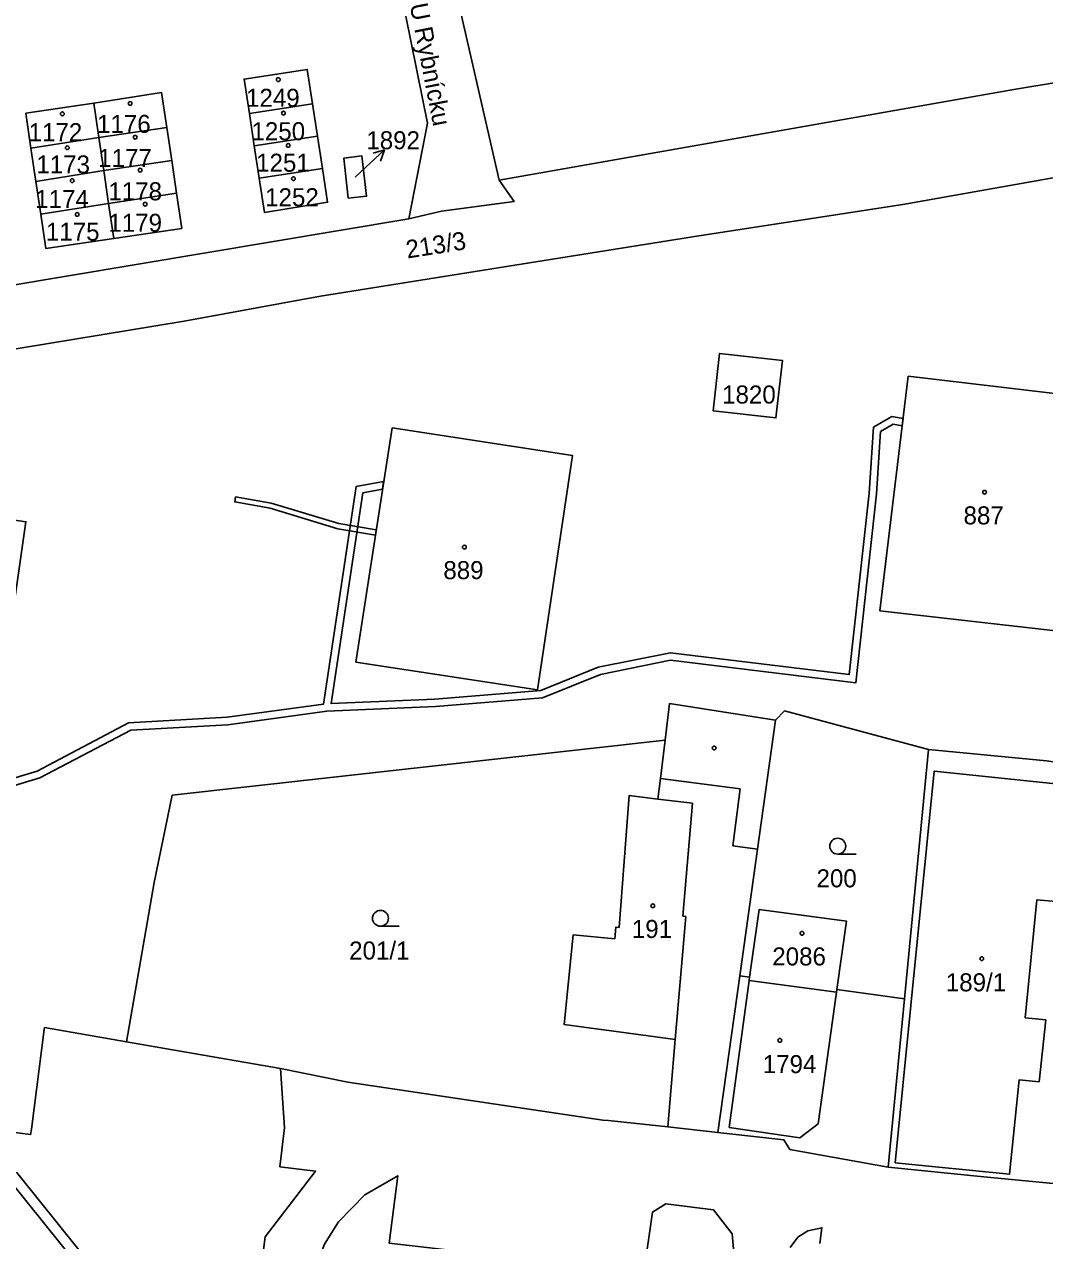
# Model space of a CAD drawing. Extents: x -680203 to -673936, y -1102717 to -1093650.
# Drawn here: x -679164.9 to -679068.7, y -1098436.4 to -1098321.8 of the extents above; entities that cross this region are included whole.
import ezdxf

# ---------------------------------------------------------------- set-up
doc = ezdxf.new("R2010")
doc.units = 0
for name, color, linetype in [('SOxx02xx_Staničení_Popis10', 7, 'Continuous'), ('SOxxxxxx_Koleje_hlavní_body_Popis10', 7, 'Continuous'), ('SOxxxxxx_Koleje_LN_parametry_Popis10', 7, 'Continuous'), ('SOxxxxxx_Koleje_param další_Popis10', 7, 'Continuous'), ('SOxxxxxx_Osa_bod_P', 7, 'Continuous'), ('SOxxxxxx_Staničení_Popis10', 7, 'Continuous'), ('x_prac', 7, 'Continuous')]:
    doc.layers.add(name, color=color, linetype=linetype)

msp = doc.modelspace()

# ---------------------------------------------------------------- linework, layer by layer
at = {"layer": 'SOxx02xx_Staničení_Popis10'}
for p, q in [((-679133.11, -1098335.71), (-679130.92, -1098333.66)), ((-679130.92, -1098333.66), (-679131.99, -1098333.98)), ((-679130.92, -1098333.66), (-679131.31, -1098334.71)), ((-679133.67, -1098336.24), (-679133.11, -1098335.71))]:
    msp.add_line(p, q, dxfattribs=at)
at = {"layer": 'SOxxxxxx_Koleje_hlavní_body_Popis10'}
for p, q in [((-679088.19, -1098400.02), (-679086.44, -1098400.02)), ((-679131.3, -1098406.82), (-679129.55, -1098406.82))]:
    msp.add_line(p, q, dxfattribs=at)
for centre in [(-679088.19, -1098399.27), (-679131.3, -1098406.07)]:
    msp.add_circle(centre, 0.75, dxfattribs=at)
at = {"layer": 'SOxxxxxx_Koleje_LN_parametry_Popis10'}
for points in [[(-679169.77, -1098394.76), (-679163.4, -1098392.84), (-679154.84, -1098388.33), (-679145.7, -1098387.83), (-679136.34, -1098386.56), (-679126.11, -1098386.12), (-679116.01, -1098385.29), (-679110.56, -1098383.08), (-679103.94, -1098381.75), (-679086.49, -1098383.88), (-679084.52, -1098366.07), (-679084.15, -1098360.21), (-679082.96, -1098359.52), (-679082.11, -1098359.66), (-679082.02, -1098358.97), (-679083.1, -1098358.79), (-679084.82, -1098359.8)], [(-679084.82, -1098359.8), (-679085.22, -1098366.01), (-679087.1, -1098383.1), (-679103.97, -1098381.04), (-679110.76, -1098382.41), (-679116.17, -1098384.6), (-679126.16, -1098385.42), (-679135.96, -1098385.84), (-679132.97, -1098365.98), (-679131.11, -1098365.64), (-679131, -1098364.91), (-679133.59, -1098365.38), (-679136.68, -1098385.9), (-679145.76, -1098387.13), (-679155.04, -1098387.64), (-679163.66, -1098392.19), (-679169.84, -1098394.05)], [(-679150.01, -1098449.39), (-679165.6, -1098430)], [(-679166.4, -1098430.6), (-679151.03, -1098449.71)]]:
    msp.add_lwpolyline(points, dxfattribs=at)
msp.add_lwpolyline([(-679144.95, -1098366.34), (-679145.04, -1098366.83), (-679141.71, -1098367.43), (-679135.32, -1098369.36), (-679131.78, -1098369.95), (-679131.7, -1098369.46), (-679135.21, -1098368.87), (-679141.59, -1098366.95)], close=True, dxfattribs=at)
at = {"layer": 'SOxxxxxx_Koleje_param další_Popis10'}
for centre in [(-679140.93, -1098327.04), (-679154.9, -1098329.28), (-679161.29, -1098330.26), (-679140.45, -1098330.19), (-679154.42, -1098332.47), (-679160.82, -1098333.46), (-679139.99, -1098333.24), (-679153.96, -1098335.57), (-679160.36, -1098336.56), (-679139.5, -1098336.37), (-679159.89, -1098339.74), (-679153.49, -1098338.78), (-679074.35, -1098365.92), (-679123.39, -1098371.09), (-679099.84, -1098390.02), (-679105.62, -1098404.89), (-679091.56, -1098407.48), (-679074.61, -1098409.87), (-679093.65, -1098417.57)]:
    msp.add_circle(centre, 0.175, dxfattribs=at)
at = {"layer": 'SOxxxxxx_Staničení_Popis10'}
for p, q in [((-679097.39, -1098393.87), (-679104.91, -1098392.9)), ((-679098.08, -1098399.23), (-679097.39, -1098393.87)), ((-679105.14, -1098394.84), (-679101.87, -1098395.23)), ((-679101.87, -1098395.23), (-679102.8, -1098405.87)), ((-679095.74, -1098399.55), (-679098.08, -1098399.23)), ((-679102.5, -1098405.9), (-679103.51, -1098417.49)), ((-679102.8, -1098405.87), (-679102.5, -1098405.9)), ((-679098.43, -1098425.79), (-679096.55, -1098411.92)), ((-679088.3, -1098413.04), (-679090.03, -1098425.43)), ((-679090.03, -1098425.43), (-679091.76, -1098426.74)), ((-679091.76, -1098426.74), (-679098.43, -1098425.79))]:
    msp.add_line(p, q, dxfattribs=at)
at = {"layer": 'x_prac'}
for p, q in [((-679125.78, -1098311.74), (-679120.11, -1098336.51)), ((-679157.85, -1098332.5), (-679158.33, -1098329.25)), ((-679143.65, -1098330.22), (-679137.7, -1098329.31)), ((-679143.65, -1098330.22), (-679143.19, -1098333.27)), ((-679137.24, -1098332.36), (-679137.7, -1098329.31)), ((-679157.85, -1098332.5), (-679151.44, -1098331.55)), ((-679150.98, -1098334.65), (-679151.44, -1098331.55)), ((-679164.25, -1098333.5), (-679157.85, -1098332.5)), ((-679157.39, -1098335.6), (-679157.85, -1098332.5)), ((-679143.19, -1098333.27), (-679137.24, -1098332.36)), ((-679136.77, -1098335.41), (-679137.24, -1098332.36)), ((-679164.25, -1098333.5), (-679163.78, -1098336.65)), ((-679143.19, -1098333.27), (-679142.72, -1098336.32)), ((-679157.39, -1098335.6), (-679150.98, -1098334.65)), ((-679150.52, -1098337.75), (-679150.98, -1098334.65)), ((-679163.78, -1098336.65), (-679157.39, -1098335.6)), ((-679156.93, -1098338.7), (-679157.39, -1098335.6)), ((-679142.72, -1098336.32), (-679136.77, -1098335.41)), ((-679163.78, -1098336.65), (-679163.33, -1098339.71)), ((-679156.93, -1098338.7), (-679150.52, -1098337.75)), ((-679163.33, -1098339.71), (-679156.93, -1098338.7)), ((-679156.44, -1098342.01), (-679156.93, -1098338.7)), ((-679079.62, -1098390.15), (-679081.9, -1098413.66)), ((-679099.48, -1098426.25), (-679097.41, -1098411.49)), ((-679096.51, -1098411.62), (-679097.41, -1098411.49)), ((-679081.9, -1098413.66), (-679088.26, -1098412.77)), ((-679104.22, -1098425.73), (-679099.48, -1098426.25))]:
    msp.add_line(p, q, dxfattribs=at)
for points in [[(-679128.63, -1098340.16), (-679126.87, -1098331.13), (-679130.44, -1098313.41)], [(-679019.35, -1098319.29), (-679071.6, -1098327.97), (-679120.11, -1098336.51)], [(-679137.7, -1098329.31), (-679138.2, -1098326.07), (-679144.15, -1098326.98), (-679143.65, -1098330.22)], [(-679158.33, -1098329.25), (-679164.73, -1098330.2), (-679164.25, -1098333.5)], [(-679151.44, -1098331.55), (-679151.95, -1098328.25), (-679158.33, -1098329.25)], [(-679134.33, -1098338.21), (-679134.75, -1098334.43), (-679133.04, -1098334.23), (-679132.6, -1098338.03), (-679134.33, -1098338.21)], [(-679063.29, -1098340.41), (-679066.13, -1098335.98), (-679082.06, -1098338.79), (-679101.3, -1098341.77), (-679136.96, -1098347.45), (-679149.82, -1098349.81), (-679185.71, -1098355.7), (-679199.74, -1098357.86), (-679234.17, -1098363.73), (-679248.19, -1098366.26), (-679260.56, -1098369.05), (-679268.5, -1098375.84), (-679272.26, -1098383.28), (-679273.78, -1098396.02), (-679274.25, -1098399.99), (-679276.49, -1098418.73), (-679277.09, -1098423.73)], [(-679142.72, -1098336.32), (-679142.22, -1098339.56), (-679136.28, -1098338.6), (-679136.77, -1098335.41)], [(-679120.11, -1098336.51), (-679118.7, -1098338.52), (-679125.55, -1098339.42), (-679128.63, -1098340.16)], [(-679156.44, -1098342.01), (-679150.03, -1098341.06), (-679150.52, -1098337.75)], [(-679291.73, -1098491.55), (-679280.23, -1098399.05), (-679274.9, -1098375.48), (-679267.59, -1098366.36), (-679263.02, -1098363.53), (-679256.44, -1098361.54), (-679128.63, -1098340.16)], [(-679163.33, -1098339.71), (-679162.84, -1098342.96), (-679156.44, -1098342.01)], [(-679099.94, -1098358.25), (-679099.34, -1098352.84), (-679093.41, -1098353.5), (-679094.01, -1098358.91), (-679099.94, -1098358.25)], [(-679081.54, -1098354.99), (-679084.22, -1098377.08), (-679067.08, -1098379.05), (-679064.54, -1098356.99), (-679081.54, -1098354.99)], [(-679130.21, -1098359.84), (-679133.63, -1098381.93), (-679116.49, -1098384.54), (-679113.18, -1098362.47), (-679130.21, -1098359.84)], [(-679185.09, -1098388), (-679167.9, -1098390.71), (-679164.73, -1098368.7), (-679181.74, -1098366.15), (-679185.09, -1098388)], [(-679094.05, -1098387.4), (-679104.04, -1098385.83), (-679104.46, -1098389.28)], [(-679079.62, -1098390.15), (-679093.22, -1098386.52), (-679094.05, -1098387.4)], [(-679097.41, -1098411.49), (-679095.74, -1098399.55), (-679094.05, -1098387.4)], [(-679104.46, -1098389.28), (-679150.95, -1098394.48), (-679152.64, -1098402.7), (-679155.24, -1098417.71)], [(-679104.46, -1098389.28), (-679104.91, -1098392.9), (-679105.14, -1098394.84), (-679107.86, -1098394.51), (-679108.8, -1098406.93), (-679109.1, -1098406.9), (-679109.21, -1098407.99), (-679113.13, -1098407.61), (-679113.97, -1098416.09), (-679110.27, -1098416.58), (-679109.78, -1098416.65), (-679103.51, -1098417.49), (-679104.22, -1098425.73)], [(-679048.39, -1098394.25), (-679068.5, -1098391.22), (-679079.62, -1098390.15)], [(-679070.53, -1098415.46), (-679068.58, -1098415.65), (-679069.2, -1098421.47), (-679071.08, -1098421.28), (-679071.99, -1098430.18), (-679082.77, -1098429.11), (-679079.11, -1098392.21), (-679058.62, -1098394.34), (-679059.69, -1098405.19), (-679069.43, -1098404.34), (-679070.53, -1098415.46)], [(-679096.51, -1098411.62), (-679095.61, -1098405.24), (-679087.35, -1098406.34), (-679088.26, -1098412.77)], [(-679088.26, -1098412.77), (-679088.3, -1098413.04), (-679096.55, -1098411.92), (-679096.51, -1098411.62)], [(-679083.44, -1098429.53), (-679082.34, -1098418.17), (-679081.9, -1098413.66)], [(-679155.24, -1098417.71), (-679162.97, -1098416.36), (-679163, -1098416.54), (-679163.96, -1098423.97), (-679164.21, -1098425.95), (-679164.28, -1098426.45), (-679169.7, -1098425.75), (-679170.49, -1098432.65)], [(-679140.73, -1098420.22), (-679153.97, -1098417.92), (-679155.24, -1098417.71)], [(-679140.79, -1098429.49), (-679140.34, -1098425.81), (-679140.73, -1098420.22)], [(-679140.73, -1098420.22), (-679134.36, -1098421.52), (-679110.32, -1098425.08), (-679109.81, -1098425.13), (-679104.22, -1098425.73)], [(-679099.48, -1098426.25), (-679093.26, -1098426.93), (-679092.72, -1098427.84), (-679083.44, -1098429.53)], [(-679143.7, -1098448.2), (-679142.18, -1098436.08), (-679137.42, -1098429.88), (-679140.79, -1098429.49)], [(-679083.44, -1098429.53), (-679074.72, -1098430.41), (-679062.34, -1098431.59), (-679057.33, -1098432.02), (-679052.8, -1098432.65)], [(-679135.27, -1098434.66), (-679136.56, -1098436.78), (-679137.25, -1098438.5), (-679136.92, -1098440.42), (-679135.89, -1098442.66), (-679134.78, -1098444.32), (-679133.18, -1098445.55), (-679131.11, -1098446.18), (-679106.54, -1098448.88), (-679103.65, -1098448.14), (-679101.21, -1098446.31), (-679099.64, -1098444.18), (-679098.51, -1098441.56), (-679097.86, -1098439.01), (-679098.15, -1098435.8), (-679099.89, -1098433.54), (-679104.39, -1098432.96), (-679105.66, -1098433.75), (-679106.48, -1098439.44), (-679130.47, -1098436.68), (-679129.67, -1098430.33), (-679132.78, -1098432.11), (-679135.27, -1098434.66)], [(-679092.68, -1098437.09), (-679091.94, -1098436.11), (-679091.02, -1098435.53), (-679089.68, -1098435.22), (-679089.87, -1098436.72)]]:
    msp.add_lwpolyline(points, dxfattribs=at)

# ---------------------------------------------------------------- texts
at = {"layer": 'SOxx02xx_Staničení_Popis10'}
msp.add_text('U Rybnícku', height=1.7, rotation=281, dxfattribs=at).set_placement((-679128.55, -1098319.99))
at = {"layer": 'SOxxxxxx_Osa_bod_P'}
for s, p in [('1249', (-679143.97, -1098329.6)), ('1176', (-679158.02, -1098332.06)), ('1172', (-679164.47, -1098332.84)), ('1250', (-679143.46, -1098332.75)), ('1892', (-679132.63, -1098333.6)), ('1177', (-679157.91, -1098335.27)), ('1173', (-679163.74, -1098335.88)), ('1251', (-679143.02, -1098335.72)), ('1178', (-679156.95, -1098338.41)), ('1252', (-679142.17, -1098338.97)), ('1174', (-679163.85, -1098339.14)), ('1175', (-679162.84, -1098342.22)), ('1179', (-679156.95, -1098341.38)), ('1820', (-679099.09, -1098357.56)), ('887', (-679076.33, -1098368.95)), ('889', (-679125.37, -1098374.11)), ('200', (-679090.19, -1098403.15)), ('191', (-679107.6, -1098407.92)), ('201/1', (-679134.25, -1098409.95)), ('2086', (-679094.36, -1098410.51)), ('189/1', (-679078, -1098412.95)), ('1794', (-679095.26, -1098420.66))]:
    msp.add_text(s, height=1.7, dxfattribs=at).set_placement(p)
msp.add_text('213/3', height=1.7, rotation=9, dxfattribs=at).set_placement((-679128.76, -1098343.9))

doc.saveas('drawing.dxf')
